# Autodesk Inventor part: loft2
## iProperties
Shininess: 64.0
Length Units: 11269
Angle Units: 11279
Time Units: 11290
Mass Units: 11283
Length Display Precision: 3
Angle Display Precision: 2
Compacted: True
Part Number: loft2
Document SubType Name: Modeling
Created: 2002-12
Designer: deepak
Density: 0.0
Volumn: 0.0
Area: 0.0
PropertySet Name: Model Information
Control State: 0
Master: False
Checked Out: False
Author: deepak
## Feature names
1. Loft4
